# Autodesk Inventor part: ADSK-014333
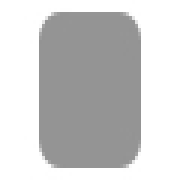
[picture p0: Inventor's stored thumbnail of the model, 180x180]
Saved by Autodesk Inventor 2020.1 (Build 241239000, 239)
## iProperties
Created: 2019-01
Part Number: ADSK-014333
Material: Stahl, weich
Document SubType Name: Modeling
Designer: lutzd
Language: de-DE
Size Designation: 5 x 39,384472 x 39,384472
Categories: <MemberInstance><Categories><Category DisplayName="Sonstige Bauteile" InternalName="5aa15e00-363f-49f2-933f-16f664388e3f" Mnemonic="OTHER"><Category DisplayName
Mass: 60.0398 g
Surface Area: 38.0412 cm^2
Volume: 7.64838 cm^3
Density: 7.85 g/cm^3
Appearance: Semi-Polished(8)
IsCustomPart: 1
Title: end cap
Author: lutzd
Revision Number: -
DocNumber: ADSK-014333
Folder: 01 - Themengebiete\Simplification\01 - Packaging machine\ADSK-014261\Frame\
VDS_Category: 3D Komponenten
VDS_NumSchm: Autodesk
Dimensions: 39,4x39,4x5 mm
Mass: 0,06 kg
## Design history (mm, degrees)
sketch "Sketch1"
  geometry: L1 (0, 20.175)-(0, -21.446); L2 (-20.203, 0)-(20.169, 0); L3 (-19.692, 19.692)-(19.692, 19.692); L4 (19.692, 19.692)-(19.692, -19.692); L5 (19.692, -19.692)-(-19.692, -19.692); L6 (-19.692, -19.692)-(-19.692, 19.692); 1 further point
  constraints: 12 end point, 2 horizontal, 2 parallel, 2 point on line, 1 perpendicular, 1 vertical
  dimensions: "d0" = 39.38447 distance between parallel lines of L5 L3 (= height); "d1" = 19.69224 distance between parallel lines of L2 L3 (= 0.5 x height); "d2" = 39.38447 distance between parallel lines of L6 L4 (= width); "d3" = 19.69224 distance between parallel lines of L6 L1 (= 0.5 x width)
extrude "Extrusion1" new body sketch "Sketch1" distance "d4" = 5 (= thickness); taper "d5" = 0 deg
fillet "Fillet1" dims "d6" = 5 (= fillet), "d7" = 0, "fillet" = 5 [user parameter; used in 1 equation term]
chamfer "Chamfer1" distance "d8" = 0 (computed from chamfer); stored, may be unused: second distance "d9" = 2, angle "d10" = 45 deg; dims "d11" = 0, "chamfer" = 0 [user parameter; used in 1 equation term]
body "Solid1"
other parameters: "thickness" = 5 [user parameter; used in 1 equation term], "width" = 39.38447 [user parameter; used in 2 equation terms], "height" = 39.38447 [user parameter; used in 2 equation terms]
